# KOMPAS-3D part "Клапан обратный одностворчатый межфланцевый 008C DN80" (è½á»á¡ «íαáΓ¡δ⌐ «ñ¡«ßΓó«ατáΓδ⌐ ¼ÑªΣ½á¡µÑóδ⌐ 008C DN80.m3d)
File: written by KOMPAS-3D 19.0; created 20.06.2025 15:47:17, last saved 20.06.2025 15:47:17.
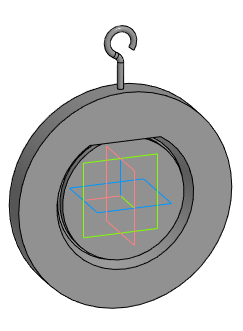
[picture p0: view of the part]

Document properties: Полное имя файла: E:\Dendor Работа Сачек\3D для проектировщиков\5.1 Тип 008C. Клапан обратный одностворчатый межфланцевый\stp_Клапан обратный одностворчатый межфланцевый 008C\Клапан обратный одностворчатый межфланцевый 008C DN80.m3d

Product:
- Part/product: Клапан обратный одностворчатый межфланцевый 008C DN80

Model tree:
1. Операция без истории:1  (labels: Клапан обратный одностворчатый межфланцевый 008C DN80)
